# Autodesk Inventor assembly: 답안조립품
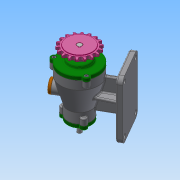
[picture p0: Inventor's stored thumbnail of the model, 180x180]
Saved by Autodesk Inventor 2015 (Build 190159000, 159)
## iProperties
Created: 2020-03
Part Number: 답안조립품
Document SubType Name: Assembly
Designer: user
Author: user
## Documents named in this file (15)
- C:\Users\user\Desktop\700306V1001\답안조립품.iam
- C:\Users\user\Desktop\700306V1001\본체.ipt
- C:\Users\user\Desktop\700306V1001\축.ipt
- C:\Users\user\Desktop\700306V1001\베어링 6200.ipt
- C:\Users\user\Desktop\700306V1001\베어링 6203.ipt
- C:\Users\user\Desktop\700306V1001\뒤커버.ipt
- C:\Users\user\Desktop\700306V1001\오일 실 10 20 7.ipt
- C:\Users\user\Desktop\700306V1001\앞커버.ipt
- C:\Users\user\Desktop\700306V1001\개스킷 B.ipt
- C:\Users\user\Desktop\700306V1001\개스킷 A.ipt
- C:\Users\user\Desktop\700306V1001\오일 실 17 30 8.ipt
- C:\Users\user\Desktop\700306V1001\키 4x4x14.ipt
- C:\Users\user\Desktop\700306V1001\스프로킷.ipt
- C:\Users\user\Desktop\700306V1001\마개.ipt
- C:\Users\user\Desktop\700306V1001\볼트 M5.ipt
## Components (2 placed, 2 different names)
1. 개스킷 B:1
2. 개스킷 A:1
